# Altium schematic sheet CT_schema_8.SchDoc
size 277 x 170 mm
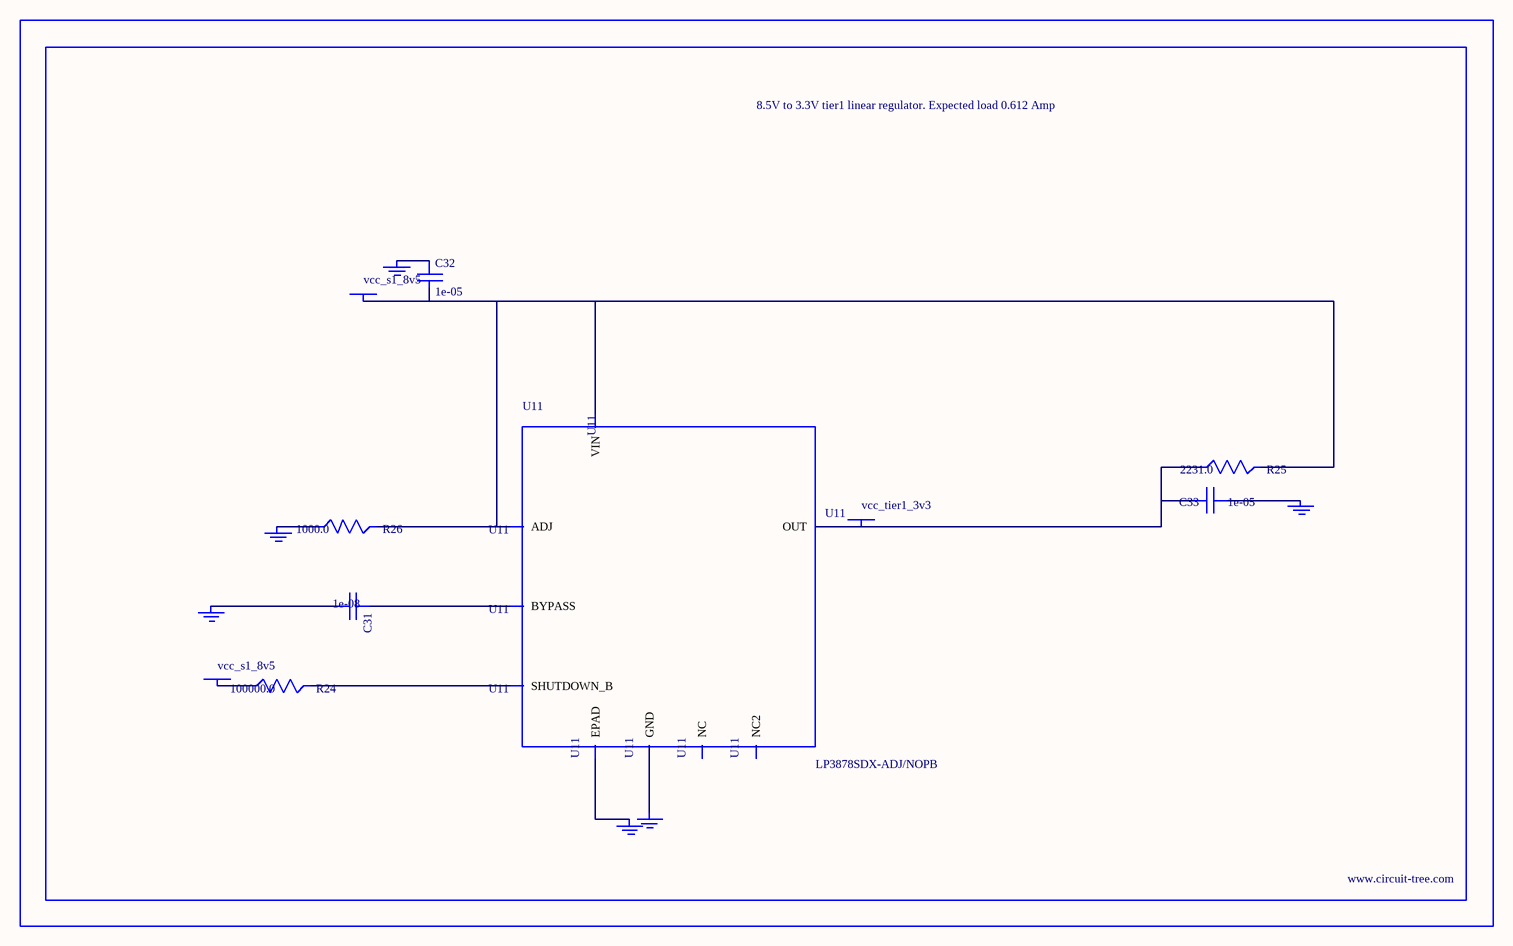
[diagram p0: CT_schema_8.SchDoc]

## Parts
BORDER7  (no value)
C31  1e-08  [C0402]
C32  1e-05  [C1206]
C33  1e-05  [C1210]
GND_INSTANCE_7_0  (no value)
GND_INSTANCE_7_1  (no value)
GND_INSTANCE_7_2  (no value)
GND_INSTANCE_7_3  (no value)
GND_INSTANCE_7_4  (no value)
GND_INSTANCE_7_5  (no value)
POWER_INSTANCE_7_0  vcc_s1_8v5
POWER_INSTANCE_7_1  vcc_s1_8v5
POWER_INSTANCE_7_2  vcc_tier1_3v3
R24  100000.0  [R0603]
R25  2231.0  [R0603]
R26  1000.0  [R0603]
U11  LP3878SDX-ADJ/NOPB  [WSON-8]

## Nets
NetC31_1: C31.1 U11.1(BYPASS)
NetC31_2: C31.2 GND_INSTANCE_7_0.0(GND)
NetC32_1: C32.1 GND_INSTANCE_7_1.0(GND)
NetC32_2: C32.2 POWER_INSTANCE_7_0.0(PWR) R25.2 R26.2 U11.4(VIN) U11.6(ADJ)
NetC33_1: C33.1 GND_INSTANCE_7_2.0(GND)
NetC33_2: C33.2 POWER_INSTANCE_7_2.0(PWR) R25.1 U11.5(OUT)
NetGND_INSTANCE_7_3_0: GND_INSTANCE_7_3.0(GND) R26.1
NetGND_INSTANCE_7_4_0: GND_INSTANCE_7_4.0(GND) U11.PAD(EPAD)
NetGND_INSTANCE_7_5_0: GND_INSTANCE_7_5.0(GND) U11.3(GND)
NetPOWER_INSTANCE_7_1_0: POWER_INSTANCE_7_1.0(PWR) R24.1
NetR24_2: R24.2 U11.8(SHUTDOWN_B)

Not connected (* = marked no-connect by the designer): U11 2(NC) 7(NC2)

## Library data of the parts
BORDER7 = BORDER_PAGE7
C31 = C0402C103K3RAC
C32 = C1206C106K3RACTU
C33 = GRM32DR61E106MA12L
GND_INSTANCE_7_0-GND_INSTANCE_7_5 = GND
POWER_INSTANCE_7_0-POWER_INSTANCE_7_2 = PWR
R24 = RC0603JR-07100KL
R25 = R25
R26 = RC0603JR-071KL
